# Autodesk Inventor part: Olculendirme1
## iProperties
Company: Autodesk, Inc.
Shininess: 64.0
Length Units: 11269
Angle Units: 11279
Time Units: 11290
Mass Units: 11283
Length Display Precision: 3
Angle Display Precision: 2
Compacted: True
Part Number: Olculendirme1
Document SubType Name: Modeling
Created: 2003-11
Catalog Web Link: www.autodesk.com
Vendor: Autodesk, Inc.
Designer: Administrator
Manufacturer: Standard
Standards Organization: Custom
Density: 1 g/cm^3
Density: 0.0
Volumn: 0.0
Area: 0.0
PropertySet Name: Model Information
Control State: 0
Master: False
Checked Out: False
Author: Administrator
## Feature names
1. Extrusion1
2. Extrusion2
3. Hole1
4. Extrusion3
5. Hole2
6. Hole3
7. Hole4
8. Hole5
9. Extrusion4
10. Chamfer1
